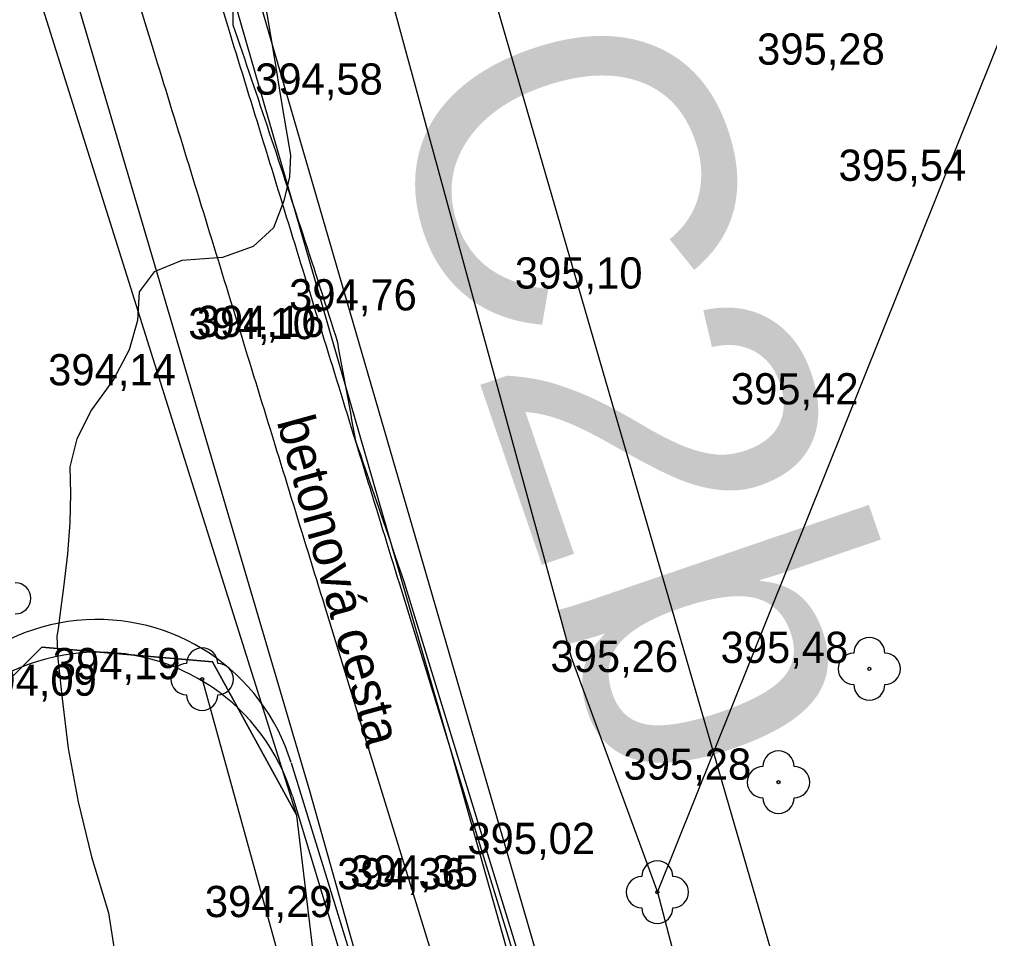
# Model space of a CAD drawing. Extents: x -574342 to -507939, y -1144044 to -1123894.
# Drawn here: x -508498.24 to -508467.17, y -1143097.38 to -1143067.94 of the extents above; entities that cross this region are included whole.
import ezdxf

# ---------------------------------------------------------------- set-up
doc = ezdxf.new("R2010")
doc.units = 0
for name, color, linetype in [('01_PARCELY_NAVRH_PC', 7, 'Continuous'), ('01_PARCELY_NAVRH_ŽP', 7, 'Continuous'), ('03_PC_POPIS_NAVRH', 7, 'Continuous'), ('1000', 7, 'Continuous'), ('15', 7, 'Continuous'), ('21', 7, 'Continuous'), ('37', 7, 'Continuous'), ('54', 7, 'Continuous'), ('55', 7, 'Continuous'), ('Level 255', 7, 'Continuous'), ('VRST VEDL', 7, 'Continuous')]:
    doc.layers.add(name, color=color, linetype=linetype)

msp = doc.modelspace()

# ---------------------------------------------------------------- linework, layer by layer
at = {"layer": '01_PARCELY_NAVRH_PC'}
for points in [[(-508499.26, -1143041.98), (-508491.15, -1143065.29), (-508474.05, -1143124.14), (-508479.46, -1143126.74), (-508483.82, -1143117.57), (-508487.01, -1143113.01), (-508489.36, -1143093.44), (-508498.08, -1143065.7), (-508506.03, -1143042.25)], [(-508539.86, -1143167.27), (-508535.17, -1143170.73), (-508529.25, -1143158.67), (-508513.07, -1143136.47), (-508505.79, -1143121.37), (-508501.93, -1143102.81), (-508501.63, -1143092.13), (-508497.53, -1143088.05), (-508492.06, -1143088.51), (-508489.36, -1143093.44), (-508498.08, -1143065.7), (-508506.03, -1143042.25), (-508507.09, -1143063.68), (-508507.1, -1143101.54), (-508510.16, -1143116.01), (-508515.95, -1143130.65), (-508519.02, -1143135.54), (-508530.41, -1143150.9), (-508533.66, -1143155.6)], [(-508539.86, -1143167.27), (-508535.17, -1143170.73), (-508529.25, -1143158.67), (-508513.07, -1143136.47), (-508505.79, -1143121.37), (-508501.93, -1143102.81), (-508501.63, -1143092.13), (-508497.53, -1143088.05), (-508492.06, -1143088.51), (-508489.36, -1143093.44), (-508498.08, -1143065.7), (-508506.03, -1143042.25), (-508507.09, -1143063.68), (-508507.1, -1143101.54), (-508510.16, -1143116.01), (-508515.95, -1143130.65), (-508519.02, -1143135.54), (-508530.41, -1143150.9), (-508533.66, -1143155.6)]]:
    msp.add_lwpolyline(points, close=True, dxfattribs=at)
at = {"layer": '01_PARCELY_NAVRH_ŽP'}
msp.add_lwpolyline([(-508540.355, -1142847.7), (-508503.94, -1143018.7), (-508499.26, -1143041.98), (-508491.15, -1143065.29), (-508474.05, -1143124.14), (-508467.92, -1143139.18), (-508459.97, -1143152.33), (-508456.09, -1143158.71), (-508451.57, -1143168.14), (-508437.66, -1143207.58), (-508425.52, -1143241.92), (-508422.7, -1143249.88), (-508420.04, -1143252.1), (-508417.38, -1143252.95), (-508415.56, -1143252.78), (-508448.24, -1143160.16), (-508453.75, -1143145.01), (-508465.11, -1143123.03), (-508471.48, -1143106.99), (-508484.55, -1143061.98), (-508495.62, -1143031.06), (-508523.23, -1142904.28), (-508534.61, -1142847.7)], dxfattribs=at)
for points in [[(-508415.56, -1143252.78), (-508448.24, -1143160.16), (-508453.75, -1143145.01), (-508465.11, -1143123.03), (-508471.48, -1143106.99), (-508484.55, -1143061.98), (-508446.15, -1143057.71)], [(-508523.79, -1143164.91), (-508521.99, -1143159.7), (-508510.09, -1143151.01), (-508503.75, -1143144.67), (-508499.11, -1143135.6), (-508498.41, -1143129.24), (-508498.01, -1143119.91), (-508496.68, -1143115.27), (-508492.61, -1143111.73), (-508487.01, -1143113.01), (-508489.36, -1143093.44), (-508492.06, -1143088.51), (-508497.53, -1143088.05), (-508501.63, -1143092.13), (-508501.93, -1143102.81), (-508505.79, -1143121.37), (-508513.07, -1143136.47), (-508529.25, -1143158.67), (-508535.17, -1143170.73), (-508530.07, -1143174.68), (-508525.32, -1143175.64)]]:
    msp.add_lwpolyline(points, close=True, dxfattribs=at)
at = {"layer": '1000'}
for points in [[(-508491.476, -1143061.682), (-508491.406, -1143068.113), (-508491.332, -1143068.329), (-508491.259, -1143068.545), (-508491.185, -1143068.76), (-508491.112, -1143068.976), (-508491.039, -1143069.192), (-508490.966, -1143069.408), (-508490.893, -1143069.624), (-508490.82, -1143069.839), (-508490.747, -1143070.055), (-508490.674, -1143070.271), (-508490.602, -1143070.487), (-508490.529, -1143070.703), (-508490.457, -1143070.919), (-508490.384, -1143071.135), (-508490.312, -1143071.352), (-508490.24, -1143071.568), (-508490.168, -1143071.784), (-508490.096, -1143072), (-508490.024, -1143072.216), (-508489.953, -1143072.433), (-508489.881, -1143072.649), (-508489.81, -1143072.865), (-508489.738, -1143073.081), (-508489.667, -1143073.298), (-508489.595, -1143073.514), (-508489.524, -1143073.731), (-508489.453, -1143073.947), (-508489.382, -1143074.164), (-508489.311, -1143074.38), (-508489.241, -1143074.597), (-508489.17, -1143074.813), (-508489.1, -1143075.03), (-508489.029, -1143075.247), (-508488.959, -1143075.463), (-508488.888, -1143075.68), (-508488.818, -1143075.897), (-508488.748, -1143076.113), (-508488.678, -1143076.33), (-508488.608, -1143076.547), (-508488.538, -1143076.764), (-508488.469, -1143076.981), (-508488.399, -1143077.198), (-508488.33, -1143077.415), (-508488.26, -1143077.632), (-508488.191, -1143077.849), (-508488.122, -1143078.066), (-508488.06, -1143078.285), (-508488.02, -1143078.511), (-508487.979, -1143078.737), (-508487.936, -1143078.962), (-508487.894, -1143079.187), (-508487.852, -1143079.413), (-508487.81, -1143079.638), (-508487.768, -1143079.864), (-508487.727, -1143080.089), (-508487.685, -1143080.315), (-508487.643, -1143080.54), (-508487.602, -1143080.766), (-508487.561, -1143080.991), (-508487.519, -1143081.217), (-508487.474, -1143081.441), (-508487.399, -1143081.657), (-508487.324, -1143081.872), (-508487.25, -1143082.087), (-508487.175, -1143082.303), (-508487.101, -1143082.518), (-508487.027, -1143082.734), (-508486.953, -1143082.949), (-508486.879, -1143083.165), (-508486.805, -1143083.38), (-508486.731, -1143083.596), (-508486.657, -1143083.812), (-508486.583, -1143084.027), (-508486.51, -1143084.243), (-508486.436, -1143084.459), (-508486.363, -1143084.674), (-508486.29, -1143084.89), (-508486.216, -1143085.106), (-508486.143, -1143085.322), (-508486.07, -1143085.538), (-508485.997, -1143085.753), (-508485.925, -1143085.969), (-508480.32, -1143104.188)], [(-508493.388, -1143062.271), (-508491.572, -1143068.165), (-508491.505, -1143068.382), (-508491.438, -1143068.6), (-508491.371, -1143068.818), (-508491.304, -1143069.035), (-508491.237, -1143069.253), (-508491.17, -1143069.471), (-508491.103, -1143069.688), (-508491.036, -1143069.906), (-508490.969, -1143070.124), (-508490.902, -1143070.341), (-508490.835, -1143070.559), (-508490.768, -1143070.777), (-508490.701, -1143070.995), (-508490.634, -1143071.212), (-508490.567, -1143071.43), (-508490.5, -1143071.648), (-508490.432, -1143071.865), (-508490.365, -1143072.083), (-508490.298, -1143072.301), (-508490.231, -1143072.518), (-508490.164, -1143072.736), (-508490.097, -1143072.954), (-508490.03, -1143073.171), (-508489.963, -1143073.389), (-508489.896, -1143073.607), (-508489.829, -1143073.825), (-508489.762, -1143074.042), (-508489.695, -1143074.26), (-508489.628, -1143074.478), (-508489.561, -1143074.695), (-508489.494, -1143074.913), (-508489.427, -1143075.131), (-508489.36, -1143075.348), (-508489.293, -1143075.566), (-508489.225, -1143075.784), (-508489.158, -1143076.001), (-508489.091, -1143076.219), (-508489.024, -1143076.437), (-508488.957, -1143076.655), (-508488.89, -1143076.872), (-508488.823, -1143077.09), (-508488.756, -1143077.308), (-508488.689, -1143077.525), (-508488.622, -1143077.743), (-508488.555, -1143077.961), (-508488.488, -1143078.178), (-508488.421, -1143078.396), (-508488.354, -1143078.614), (-508488.287, -1143078.831), (-508488.22, -1143079.049), (-508488.153, -1143079.267), (-508488.085, -1143079.485), (-508488.018, -1143079.702), (-508487.951, -1143079.92), (-508487.884, -1143080.138), (-508487.817, -1143080.355), (-508487.75, -1143080.573), (-508487.683, -1143080.791), (-508487.616, -1143081.008), (-508487.549, -1143081.226), (-508487.482, -1143081.444), (-508487.415, -1143081.661), (-508487.348, -1143081.879), (-508487.281, -1143082.097), (-508487.214, -1143082.315), (-508487.147, -1143082.532), (-508487.08, -1143082.75), (-508487.013, -1143082.968), (-508486.946, -1143083.185), (-508486.878, -1143083.403), (-508486.811, -1143083.621), (-508486.744, -1143083.838), (-508486.677, -1143084.056), (-508486.61, -1143084.274), (-508486.543, -1143084.492), (-508486.476, -1143084.709), (-508486.409, -1143084.927), (-508486.342, -1143085.145), (-508486.275, -1143085.362), (-508486.208, -1143085.58), (-508486.141, -1143085.798), (-508486.074, -1143086.015), (-508480.463, -1143104.231)], [(-508489.541, -1143091.744), (-508485.241, -1143105.703)], [(-508489.501, -1143092.82), (-508485.568, -1143105.804)]]:
    msp.add_lwpolyline(points, dxfattribs=at)
for centre, start, end in [((-508495.753, -1143093.657), 17.1206, 174.3613), ((-508495.722, -1143094.705), 16.8507, 172.5454)]:
    msp.add_arc(centre, 6.5, start, end, dxfattribs=at)
at = {"layer": '21'}
msp.add_lwpolyline([(-508495.777, -1143063.007), (-508493.962, -1143068.9), (-508493.895, -1143069.118), (-508493.828, -1143069.336), (-508493.76, -1143069.554), (-508493.693, -1143069.771), (-508493.626, -1143069.989), (-508493.559, -1143070.207), (-508493.492, -1143070.424), (-508493.425, -1143070.642), (-508493.358, -1143070.86), (-508493.291, -1143071.077), (-508493.224, -1143071.295), (-508493.157, -1143071.513), (-508493.09, -1143071.73), (-508493.023, -1143071.948), (-508492.956, -1143072.166), (-508492.889, -1143072.384), (-508492.822, -1143072.601), (-508492.755, -1143072.819), (-508492.688, -1143073.037), (-508492.621, -1143073.254), (-508492.553, -1143073.472), (-508492.486, -1143073.69), (-508492.419, -1143073.907), (-508492.352, -1143074.125), (-508492.285, -1143074.343), (-508492.218, -1143074.56), (-508492.151, -1143074.778), (-508492.084, -1143074.996), (-508492.017, -1143075.214), (-508491.95, -1143075.431), (-508491.883, -1143075.649), (-508491.816, -1143075.867), (-508491.749, -1143076.084), (-508491.682, -1143076.302), (-508491.615, -1143076.52), (-508491.548, -1143076.737), (-508491.481, -1143076.955), (-508491.413, -1143077.173), (-508491.346, -1143077.391), (-508491.279, -1143077.608), (-508491.212, -1143077.826), (-508491.145, -1143078.044), (-508491.078, -1143078.261), (-508491.011, -1143078.479), (-508490.944, -1143078.697), (-508490.877, -1143078.914), (-508490.81, -1143079.132), (-508490.743, -1143079.35), (-508490.676, -1143079.567), (-508490.609, -1143079.785), (-508490.542, -1143080.003), (-508490.475, -1143080.221), (-508490.408, -1143080.438), (-508490.341, -1143080.656), (-508490.274, -1143080.874), (-508490.206, -1143081.091), (-508490.139, -1143081.309), (-508490.072, -1143081.527), (-508490.005, -1143081.744), (-508489.938, -1143081.962), (-508489.871, -1143082.18), (-508489.804, -1143082.397), (-508489.737, -1143082.615), (-508489.67, -1143082.833), (-508489.603, -1143083.051), (-508489.536, -1143083.268), (-508489.469, -1143083.486), (-508489.402, -1143083.704), (-508489.335, -1143083.921), (-508489.268, -1143084.139), (-508489.201, -1143084.357), (-508489.134, -1143084.574), (-508489.067, -1143084.792), (-508488.999, -1143085.01), (-508488.932, -1143085.227), (-508488.865, -1143085.445), (-508488.798, -1143085.663), (-508488.731, -1143085.881), (-508488.664, -1143086.098), (-508488.597, -1143086.316), (-508488.53, -1143086.534), (-508488.463, -1143086.751), (-508482.852, -1143104.967)], dxfattribs=at)
at = {"layer": '37'}
msp.add_lwpolyline([(-508476.03, -1143123.74), (-508475.36, -1143123.53), (-508484.42, -1143091.34), (-508494.04, -1143058.06), (-508495.34, -1143058.46), (-508498.68, -1143059.63), (-508488.94, -1143092.68), (-508479.81, -1143125.14), (-508478.76, -1143124.67)], dxfattribs=at)
msp.add_lwpolyline([(-508476.03, -1143123.74), (-508475.36, -1143123.53), (-508484.42, -1143091.34), (-508494.04, -1143058.06), (-508495.34, -1143058.46), (-508498.68, -1143059.63), (-508488.94, -1143092.68), (-508479.81, -1143125.14), (-508478.76, -1143124.67)], dxfattribs=at)
at = {"layer": '54'}
for centre in [(-508471.02, -1143088.74), (-508492.39, -1143089.07), (-508473.93, -1143092.37), (-508477.81, -1143095.89)]:
    msp.add_circle(centre, 0.05, dxfattribs=at)
for centre, start, end in [((-508498.38, -1143086.48), 270, 90), ((-508471.02, -1143088.24), 0, 180), ((-508492.39, -1143088.57), 0, 180), ((-508471.52, -1143088.74), 90, 270), ((-508470.52, -1143088.74), 270, 90), ((-508492.89, -1143089.07), 90, 270), ((-508491.89, -1143089.07), 270, 90), ((-508471.02, -1143089.24), 180, 0), ((-508492.39, -1143089.57), 180, 0), ((-508473.93, -1143091.87), 0, 180), ((-508474.43, -1143092.37), 90, 270), ((-508473.43, -1143092.37), 270, 90), ((-508473.93, -1143092.87), 180, 0), ((-508477.81, -1143095.39), 0, 180), ((-508478.31, -1143095.89), 90, 270), ((-508477.31, -1143095.89), 270, 90), ((-508477.81, -1143096.39), 180, 0)]:
    msp.add_arc(centre, 0.5, start, end, dxfattribs=at)
at = {"layer": '55'}
for p, q in [((-508477.81, -1143095.89), (-508464.59, -1143062.97)), ((-508477.81, -1143095.89), (-508464.59, -1143062.97)), ((-508492.39, -1143089.07), (-508487.42, -1143107.11)), ((-508492.39, -1143089.07), (-508487.42, -1143107.11))]:
    msp.add_line(p, q, dxfattribs=at)
msp.add_lwpolyline([(-508486.89, -1143065.21), (-508480.57, -1143088.37), (-508477.81, -1143095.89), (-508475.78, -1143103.63), (-508468.39, -1143122.87), (-508456.91, -1143145.22), (-508451.68, -1143159.54), (-508438.58, -1143205.02)], dxfattribs=at)
msp.add_lwpolyline([(-508486.89, -1143065.21), (-508480.57, -1143088.37), (-508477.81, -1143095.89), (-508475.78, -1143103.63), (-508468.39, -1143122.87), (-508456.91, -1143145.22), (-508451.68, -1143159.54), (-508438.58, -1143205.02)], dxfattribs=at)
at = {"layer": 'VRST VEDL'}
msp.add_lwpolyline([(-508490.425, -1143067.117), (-508490.099, -1143069.087), (-508489.846, -1143070.605), (-508489.666, -1143071.67), (-508489.558, -1143072.283), (-508489.595, -1143072.978), (-508489.777, -1143073.754), (-508490.104, -1143074.611), (-508490.757, -1143075.215), (-508491.737, -1143075.564), (-508493.043, -1143075.659), (-508493.932, -1143076.028), (-508494.404, -1143076.67), (-508494.46, -1143077.586), (-508494.734, -1143078.52), (-508495.227, -1143079.471), (-508495.939, -1143080.441), (-508496.406, -1143081.372), (-508496.628, -1143082.265), (-508496.604, -1143083.12), (-508496.631, -1143084.05), (-508496.709, -1143085.056), (-508496.836, -1143086.138), (-508496.936, -1143086.937), (-508497.007, -1143087.455), (-508497.05, -1143087.691), (-508497.01, -1143088.408), (-508496.888, -1143089.606), (-508496.683, -1143091.285), (-508496.366, -1143093.003), (-508495.934, -1143094.759), (-508495.39, -1143096.554), (-508495.099, -1143098.401)], dxfattribs=at)

# ---------------------------------------------------------------- texts
at = {"layer": '03_PC_POPIS_NAVRH'}
msp.add_text('C2b', height=10, rotation=288.8853, dxfattribs=at).set_placement((-508486.823, -1143069.87))
at = {"layer": '15'}
msp.add_text('betonová cesta', height=1.2, rotation=285.3903, dxfattribs=at).set_placement((-508490.008, -1143080.813))
msp.add_text('betonová cesta', height=1.2, rotation=285.3903, dxfattribs=at).set_placement((-508490.008, -1143080.813))
at = {"layer": 'Level 255'}
for s, p in [('395,28', (-508474.615, -1143069.39)), ('394,58', (-508490.695, -1143070.35)), ('395,54', (-508472.005, -1143073.11)), ('395,10', (-508482.375, -1143076.56)), ('394,76', (-508489.605, -1143077.26)), ('394,10', (-508492.835, -1143078.18)), ('394,16', (-508492.565, -1143078.11)), ('394,14', (-508497.325, -1143079.66)), ('395,42', (-508475.455, -1143080.27)), ('395,48', (-508475.785, -1143088.55)), ('395,26', (-508481.235, -1143088.84)), ('394,19', (-508497.175, -1143089.07)), ('394,09', (-508499.855, -1143089.6)), ('395,28', (-508478.895, -1143092.29)), ('395,02', (-508483.895, -1143094.67)), ('394,35', (-508487.645, -1143095.71)), ('394,36', (-508488.065, -1143095.8)), ('394,29', (-508492.305, -1143096.69))]:
    msp.add_text(s, height=1, dxfattribs=at).set_placement(p)

doc.saveas('drawing.dxf')
